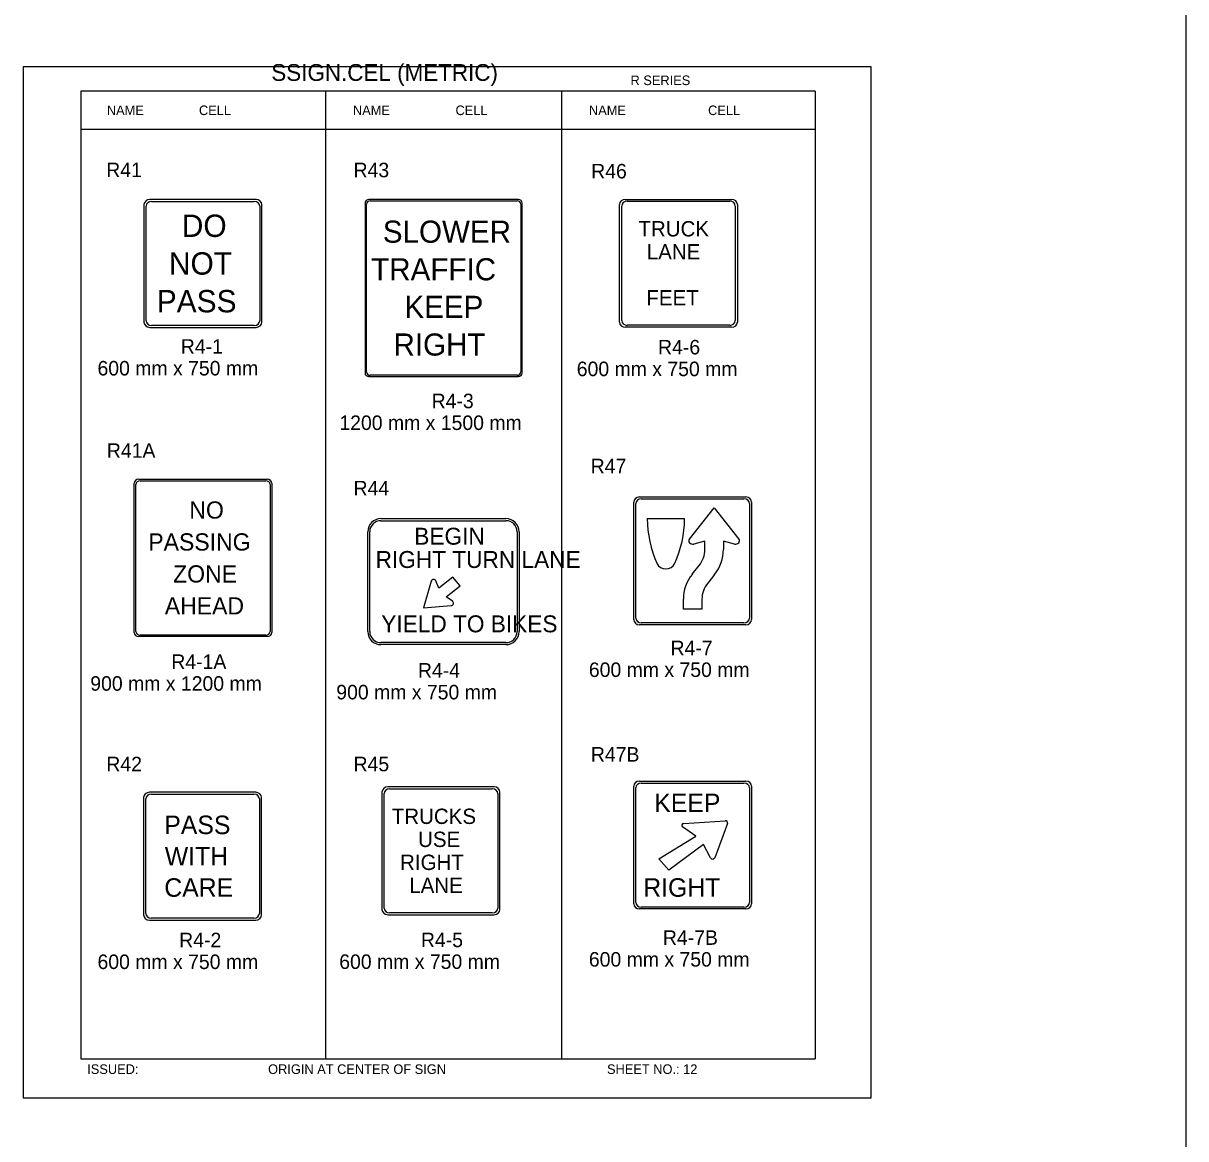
# Model space of a CAD drawing. Extents: x -12 to 6962, y -3756 to 679.
# Drawn here: x 1018.1 to 1258.3, y -13.5 to 217 of the extents above; entities that cross this region are included whole.
import ezdxf

# ---------------------------------------------------------------- set-up
doc = ezdxf.new("R2010")
doc.units = 0
for name, color, linetype in [('Level 1', 7, 'Continuous'), ('Level 2', 7, 'Continuous'), ('Level 3', 7, 'Continuous'), ('Level 63', 7, 'Continuous')]:
    doc.layers.add(name, color=color, linetype=linetype)

msp = doc.modelspace()

# ---------------------------------------------------------------- linework, layer by layer
at = {"layer": 'Level 1'}
for p, q in [((1181.72, 203.02), (1029.96, 203.02)), ((1029.96, 203.02), (1029.96, 3.02)), ((1080.55, 203.02), (1080.55, 3.02)), ((1129.33, 203.02), (1129.33, 3.02)), ((1181.72, 203.02), (1181.72, 3.02)), ((1181.72, 195.1), (1029.96, 195.1)), ((1044.61, 180.21), (1065.83, 180.21)), ((1089.77, 180.32), (1120.17, 180.32)), ((1142.89, 180.25), (1164.11, 180.25)), ((1043.48, 155.56), (1043.48, 179.24)), ((1066.96, 179.24), (1066.96, 155.56)), ((1089.02, 144.97), (1089.02, 179.65)), ((1120.93, 179.65), (1120.93, 144.97)), ((1141.76, 155.59), (1141.76, 179.27)), ((1165.24, 179.27), (1165.24, 155.59)), ((1055.22, 167.4), (1055.22, 167.4)), ((1153.5, 167.43), (1153.5, 167.43)), ((1104.97, 162.31), (1104.97, 162.31)), ((1065.83, 154.58), (1044.61, 154.58)), ((1164.11, 154.62), (1142.89, 154.62)), ((1120.17, 144.29), (1089.77, 144.29)), ((1041.35, 91.34), (1041.35, 121.74)), ((1042.23, 122.49), (1068.22, 122.49)), ((1069.09, 121.74), (1069.09, 91.34)), ((1144.69, 94.1), (1144.69, 117.78)), ((1145.82, 118.75), (1167.04, 118.75)), ((1168.17, 117.78), (1168.17, 94.1)), ((1155.76, 110.44), (1160.87, 116.87)), ((1160.87, 116.87), (1166, 110.44)), ((1092.01, 114.24), (1117.84, 114.24)), ((1147.06, 114.69), (1154.74, 114.69)), ((1089.7, 91.35), (1089.7, 111.93)), ((1120.15, 111.93), (1120.15, 91.35)), ((1158.96, 110.02), (1156.66, 109.41)), ((1158.96, 108.28), (1158.96, 110.02)), ((1165.1, 109.41), (1162.8, 110.02)), ((1162.8, 110.02), (1162.8, 108.28)), ((1055.22, 106.54), (1055.22, 106.54)), ((1156.43, 105.94), (1156.43, 105.94)), ((1156.36, 103.21), (1157.77, 104.97)), ((1104.93, 101.64), (1104.93, 101.64)), ((1160.95, 103.09), (1159.54, 101.33)), ((1154.51, 95.94), (1154.51, 98.02)), ((1158.35, 98.02), (1158.35, 95.94)), ((1158.35, 95.94), (1154.51, 95.94)), ((1167.04, 93.12), (1145.82, 93.12)), ((1068.22, 90.59), (1042.23, 90.59)), ((1117.84, 89.04), (1092.01, 89.04)), ((1044.54, 57.72), (1065.76, 57.72)), ((1092.68, 34.17), (1092.68, 57.85)), ((1093.8, 58.82), (1115.03, 58.82)), ((1116.15, 57.85), (1116.15, 34.17)), ((1144.69, 35.36), (1144.69, 59.04)), ((1145.82, 60.01), (1167.04, 60.01)), ((1168.17, 59.04), (1168.17, 35.36)), ((1043.41, 33.06), (1043.41, 56.74)), ((1066.89, 56.74), (1066.89, 33.06)), ((1157.08, 49.04), (1154.35, 50.97)), ((1154.63, 51.68), (1163.17, 52.19)), ((1163.64, 51.68), (1160.98, 44.58)), ((1149.44, 44.34), (1157.08, 49.04)), ((1104.42, 46.01), (1104.42, 46.01)), ((1158.64, 47.32), (1151.54, 42.04)), ((1156.43, 47.2), (1156.43, 47.2)), ((1160.13, 44.55), (1158.64, 47.32)), ((1055.15, 44.9), (1055.15, 44.9)), ((1151.54, 42.04), (1149.44, 44.34)), ((1167.04, 34.38), (1145.82, 34.38)), ((1065.76, 32.08), (1044.54, 32.08)), ((1115.03, 33.19), (1093.8, 33.19)), ((1029.96, 3.02), (1181.72, 3.02))]:
    msp.add_line(p, q, dxfattribs=at)
for points in [[(1102.42, 101.72), (1100.8, 96.21), (1106.53, 96.68)], [(1106.77, 97.63), (1105.47, 98.47), (1108.36, 100.78), (1106.89, 102.56), (1104, 100.31), (1103.37, 101.83), (1103.37, 101.83)]]:
    msp.add_lwpolyline(points, dxfattribs=at)
for centre, radius, start, end in [((1092.01, 111.93), 2.31, 90, 180), ((1117.84, 111.93), 2.31, 0, 90), ((1102.92, 101.6), 0.508, 26.3193, 166.5712), ((1106.48, 97.2), 0.519, 275.5576, 56.0993), ((1092.01, 91.35), 2.31, 180, 270), ((1117.84, 91.35), 2.31, 270, 0)]:
    msp.add_arc(centre, radius, start, end, dxfattribs=at)
for centre, major_axis, ratio, start_param, end_param in [((1044.61, 179.24), (-1.13, 0), 0.866667, 4.712389, 6.283185), ((1065.83, 179.24), (-1.13, 0), 0.866667, 3.141593, 4.712389), ((1089.77, 179.65), (-0.752, 0), 0.9, 4.712389, 6.283185), ((1120.17, 179.65), (-0.752, 0), 0.9, 3.141593, 4.712389), ((1142.89, 179.27), (-1.13, 0), 0.866667, 4.712389, 6.283185), ((1164.11, 179.27), (-1.13, 0), 0.866667, 3.141593, 4.712389), ((1044.61, 155.56), (1.13, 0), 0.866667, 3.141593, 4.712389), ((1065.83, 155.56), (1.13, 0), 0.866667, 4.712389, 6.283185), ((1142.89, 155.59), (1.13, 0), 0.866667, 3.141593, 4.712389), ((1164.11, 155.59), (1.13, 0), 0.866667, 4.712389, 6.283185), ((1089.77, 144.97), (0.752, 0), 0.9, 3.141593, 4.712389), ((1120.17, 144.97), (0.752, 0), 0.9, 4.712389, 6.283185), ((1042.23, 121.74), (-0.877, 0), 0.857082, 4.712389, 6.283185), ((1068.22, 121.74), (-0.877, 0), 0.857082, 3.141593, 4.712389), ((1145.82, 117.78), (-1.13, 0), 0.866667, 4.712389, 6.283185), ((1167.04, 117.78), (-1.13, 0), 0.866667, 3.141593, 4.712389), ((1175.82, 114.58), (28.76, 0), 0.866667, 3.137591, 3.522165), ((1125.87, 114.6), (-28.87, 0), 0.866667, 2.761745, 3.144869), ((1156.42, 110.08), (0.801, 0), 0.866667, 2.568526, 5.001662), ((1152.23, 108.28), (6.72, 0), 0.866667, 5.679854, 6.283438), ((1152.17, 108.28), (10.62, 0), 0.866667, 5.684484, 6.282418), ((1165.32, 110.08), (-0.801, 0), 0.866667, 1.281523, 3.71466), ((1150.9, 105.93), (1.92, 0), 0.866667, 3.517117, 5.907661), ((1165.08, 98.02), (-10.57, 0), 0.866667, 5.680583, 6.283185), ((1165.04, 98.02), (6.69, 0), 0.866667, 2.533053, 3.14213), ((1145.82, 94.1), (1.13, 0), 0.866667, 3.141593, 4.712389), ((1167.04, 94.1), (1.13, 0), 0.866667, 4.712389, 6.283185), ((1042.23, 91.34), (0.877, 0), 0.857082, 3.141593, 4.712389), ((1068.22, 91.34), (0.877, 0), 0.857082, 4.712389, 6.283185), ((1044.54, 56.74), (-1.13, 0), 0.866667, 4.712389, 6.283185), ((1065.76, 56.74), (-1.13, 0), 0.866667, 3.141593, 4.712389), ((1093.8, 57.85), (-1.13, 0), 0.866667, 4.712389, 6.283185), ((1115.03, 57.85), (-1.13, 0), 0.866667, 3.141593, 4.712389), ((1145.82, 59.04), (-1.13, 0), 0.866667, 4.712389, 6.283185), ((1167.04, 59.04), (-1.13, 0), 0.866667, 3.141593, 4.712389), ((1154.63, 51.28), (0.469, 0), 0.866667, 1.619302, 4.048856), ((1163.2, 51.8), (-0.473, 0), 0.866667, 2.836574, 4.787444), ((1160.55, 44.71), (0.469, 0), 0.866667, 3.559508, 5.980834), ((1093.8, 34.17), (1.13, 0), 0.866667, 3.141593, 4.712389), ((1115.03, 34.17), (1.13, 0), 0.866667, 4.712389, 6.283185), ((1145.82, 35.36), (1.13, 0), 0.866667, 3.141593, 4.712389), ((1167.04, 35.36), (1.13, 0), 0.866667, 4.712389, 6.283185), ((1044.54, 33.06), (1.13, 0), 0.866667, 3.141593, 4.712389), ((1065.76, 33.06), (1.13, 0), 0.866667, 4.712389, 6.283185)]:
    msp.add_ellipse(centre, major_axis=major_axis, ratio=ratio, start_param=start_param, end_param=end_param, dxfattribs=at)
at = {"layer": 'Level 3'}
for p, q in [((1258.34, 661.66), (1258.34, -1225.34)), ((1066.19, 180.61), (1044.25, 180.61)), ((1120.41, 180.6), (1089.53, 180.6)), ((1142.53, 180.64), (1164.47, 180.64)), ((1043.03, 179.55), (1043.03, 155.25)), ((1067.41, 155.25), (1067.41, 179.55)), ((1088.72, 179.86), (1088.72, 144.75)), ((1121.23, 144.75), (1121.23, 179.86)), ((1141.31, 155.28), (1141.31, 179.58)), ((1165.69, 179.58), (1165.69, 155.28)), ((1044.25, 154.19), (1066.19, 154.19)), ((1164.47, 154.22), (1142.53, 154.22)), ((1089.53, 144.02), (1120.41, 144.02)), ((1041.94, 122.8), (1068.5, 122.8)), ((1041, 91.1), (1041, 121.98)), ((1069.44, 121.98), (1069.44, 91.1)), ((1144.24, 93.79), (1144.24, 118.09)), ((1145.46, 119.15), (1167.4, 119.15)), ((1168.62, 118.09), (1168.62, 93.79)), ((1092.01, 114.66), (1117.84, 114.66)), ((1089.28, 91.35), (1089.28, 111.93)), ((1120.57, 111.93), (1120.57, 91.35)), ((1167.4, 92.73), (1145.46, 92.73)), ((1068.5, 90.29), (1041.94, 90.29)), ((1117.84, 88.62), (1092.01, 88.62)), ((1145.46, 60.41), (1167.4, 60.41)), ((1066.12, 58.11), (1044.18, 58.11)), ((1092.22, 58.16), (1092.22, 33.86)), ((1115.39, 59.22), (1093.44, 59.22)), ((1116.61, 33.86), (1116.61, 58.16)), ((1144.24, 35.05), (1144.24, 59.35)), ((1168.62, 59.35), (1168.62, 35.05)), ((1042.96, 57.05), (1042.96, 32.75)), ((1067.34, 32.75), (1067.34, 57.05)), ((1167.4, 33.99), (1145.46, 33.99)), ((1044.18, 31.69), (1066.12, 31.69)), ((1093.44, 32.8), (1115.39, 32.8))]:
    msp.add_line(p, q, dxfattribs=at)
for centre, start, end in [((1092.01, 111.93), 90, 180), ((1117.84, 111.93), 0, 90), ((1092.01, 91.35), 180, 270), ((1117.84, 91.35), 270, 0)]:
    msp.add_arc(centre, 2.73, start, end, dxfattribs=at)
for centre, major_axis, ratio, start_param, end_param in [((1044.25, 179.55), (-1.22, 0), 0.866667, 4.712389, 6.283185), ((1066.19, 179.55), (-1.22, 0), 0.866667, 3.141593, 4.712389), ((1089.53, 179.86), (-0.813, 0), 0.9, 4.712389, 6.283185), ((1120.41, 179.86), (-0.813, 0), 0.9, 3.141593, 4.712389), ((1142.53, 179.58), (-1.22, 0), 0.866667, 4.712389, 6.283185), ((1164.47, 179.58), (-1.22, 0), 0.866667, 3.141593, 4.712389), ((1044.25, 155.25), (1.22, 0), 0.866667, 3.141593, 4.712389), ((1066.19, 155.25), (1.22, 0), 0.866667, 4.712389, 6.283185), ((1142.53, 155.28), (1.22, 0), 0.866667, 3.141593, 4.712389), ((1164.47, 155.28), (1.22, 0), 0.866667, 4.712389, 6.283185), ((1089.53, 144.75), (0.813, 0), 0.9, 3.141593, 4.712389), ((1120.41, 144.75), (0.813, 0), 0.9, 4.712389, 6.283185), ((1041.94, 121.98), (-0.948, 0), 0.857082, 4.712389, 6.283185), ((1068.5, 121.98), (-0.948, 0), 0.857082, 3.141593, 4.712389), ((1145.46, 118.09), (-1.22, 0), 0.866667, 4.712389, 6.283185), ((1167.4, 118.09), (-1.22, 0), 0.866667, 3.141593, 4.712389), ((1145.46, 93.79), (1.22, 0), 0.866667, 3.141593, 4.712389), ((1167.4, 93.79), (1.22, 0), 0.866667, 4.712389, 6.283185), ((1041.94, 91.1), (0.948, 0), 0.857082, 3.141593, 4.712389), ((1068.5, 91.1), (0.948, 0), 0.857082, 4.712389, 6.283185), ((1145.46, 59.35), (-1.22, 0), 0.866667, 4.712389, 6.283185), ((1167.4, 59.35), (-1.22, 0), 0.866667, 3.141593, 4.712389), ((1044.18, 57.05), (-1.22, 0), 0.866667, 4.712389, 6.283185), ((1066.12, 57.05), (-1.22, 0), 0.866667, 3.141593, 4.712389), ((1093.44, 58.16), (-1.22, 0), 0.866667, 4.712389, 6.283185), ((1115.39, 58.16), (-1.22, 0), 0.866667, 3.141593, 4.712389), ((1093.44, 33.86), (1.22, 0), 0.866667, 3.141593, 4.712389), ((1115.39, 33.86), (1.22, 0), 0.866667, 4.712389, 6.283185), ((1145.46, 35.05), (1.22, 0), 0.866667, 3.141593, 4.712389), ((1167.4, 35.05), (1.22, 0), 0.866667, 4.712389, 6.283185), ((1044.18, 32.75), (1.22, 0), 0.866667, 3.141593, 4.712389), ((1066.12, 32.75), (1.22, 0), 0.866667, 4.712389, 6.283185)]:
    msp.add_ellipse(centre, major_axis=major_axis, ratio=ratio, start_param=start_param, end_param=end_param, dxfattribs=at)
at = {"layer": 'Level 63'}
msp.add_lwpolyline([(1018.09, -5.05), (1193.35, -5.05), (1193.35, 208.05), (1018.09, 208.05)], close=True, dxfattribs=at)

# ---------------------------------------------------------------- texts
at = {"layer": 'Level 1'}
for s, height, p in [('DO', 4.623, (1050.85, 172.88)), ('SLOWER', 4.572, (1092.4, 171.68)), ('TRUCK', 3.17, (1145.22, 172.98)), ('LANE', 3.17, (1146.95, 168.22)), ('NOT', 4.623, (1048.19, 165.09)), ('TRAFFIC', 4.572, (1089.99, 163.91)), ('PASS', 4.623, (1045.67, 157.29)), ('FEET', 3.17, (1146.86, 158.71)), ('KEEP', 4.572, (1096.86, 156.14)), ('RIGHT', 4.572, (1094.6, 148.36)), ('NO', 3.556, (1052.41, 114.67)), ('PASSING', 3.556, (1043.93, 108.07)), ('BEGIN', 3.5, (1098.9, 109.28)), ('RIGHT TURN LANE', 3.5, (1090.9, 104.47)), ('ZONE', 3.556, (1049.06, 101.46)), ('AHEAD', 3.556, (1047.34, 94.86)), ('YIELD TO BIKES', 3.5, (1092.08, 91.17)), ('KEEP', 3.83, (1148.5, 54.01)), ('PASS', 3.83, (1047.24, 49.46)), ('TRUCKS', 3.17, (1094.24, 51.56)), ('USE', 3.17, (1099.68, 46.8)), ('WITH', 3.83, (1047.34, 42.98)), ('RIGHT', 3.17, (1095.96, 42.05)), ('CARE', 3.83, (1047.24, 36.51)), ('LANE', 3.17, (1097.86, 37.29)), ('RIGHT', 3.83, (1146.22, 36.52))]:
    msp.add_text(s, height=height, dxfattribs=at).set_placement(p)
at = {"layer": 'Level 2'}
for s, p in [('R41', (1035.24, 185.24)), ('R43', (1086.35, 185.21)), ('R46', (1135.46, 184.98)), ('R41A', (1035.37, 127.23)), ('R47', (1135.36, 124.04)), ('R44', (1086.35, 119.47)), ('R47B', (1135.4, 64.45)), ('R42', (1035.26, 62.45)), ('R45', (1086.35, 62.45))]:
    msp.add_text(s, height=3, dxfattribs=at).set_placement(p)
at = {"layer": 'Level 3'}
for s, height, p in [('SSIGN.CEL (METRIC)', 3.4642, (1069.35, 205.13)), ('R SERIES', 1.979, (1143.59, 204.26)), ('NAME', 1.98, (1035.36, 198.06)), ('CELL', 1.98, (1054.4, 198.06)), ('NAME', 1.98, (1086.22, 198.06)), ('CELL', 1.98, (1107.42, 198.06)), ('NAME', 1.98, (1135, 198.06)), ('CELL', 1.98, (1159.62, 198.06)), ('R4-1', 3, (1050.65, 148.75)), ('R4-6', 3, (1149.28, 148.61)), ('600 mm x 750 mm', 3, (1033.43, 144.25)), ('600 mm x 750 mm', 3, (1132.48, 144.11)), ('R4-3', 3, (1102.49, 137.48)), ('1200 mm x 1500 mm', 3, (1083.42, 132.98)), ('R4-7', 3, (1151.86, 86.44)), ('R4-1A', 3, (1048.69, 83.6)), ('R4-4', 3, (1099.66, 81.81)), ('600 mm x 750 mm', 3, (1134.98, 81.94)), ('900 mm x 1200 mm', 3, (1031.94, 79.1)), ('900 mm x 750 mm', 3, (1082.78, 77.31)), ('R4-2', 3, (1050.31, 26.08)), ('R4-5', 3, (1100.27, 26.1)), ('R4-7B', 3, (1150.28, 26.58)), ('600 mm x 750 mm', 3, (1033.43, 21.58)), ('600 mm x 750 mm', 3, (1083.39, 21.6)), ('600 mm x 750 mm', 3, (1134.98, 22.08)), ('ISSUED:', 1.98, (1031.31, -0.1)), ('ORIGIN AT CENTER OF SIGN', 1.9795, (1068.69, -0.1)), ('SHEET NO.: 12', 1.9795, (1138.73, -0.1))]:
    msp.add_text(s, height=height, dxfattribs=at).set_placement(p)

doc.saveas('drawing.dxf')
